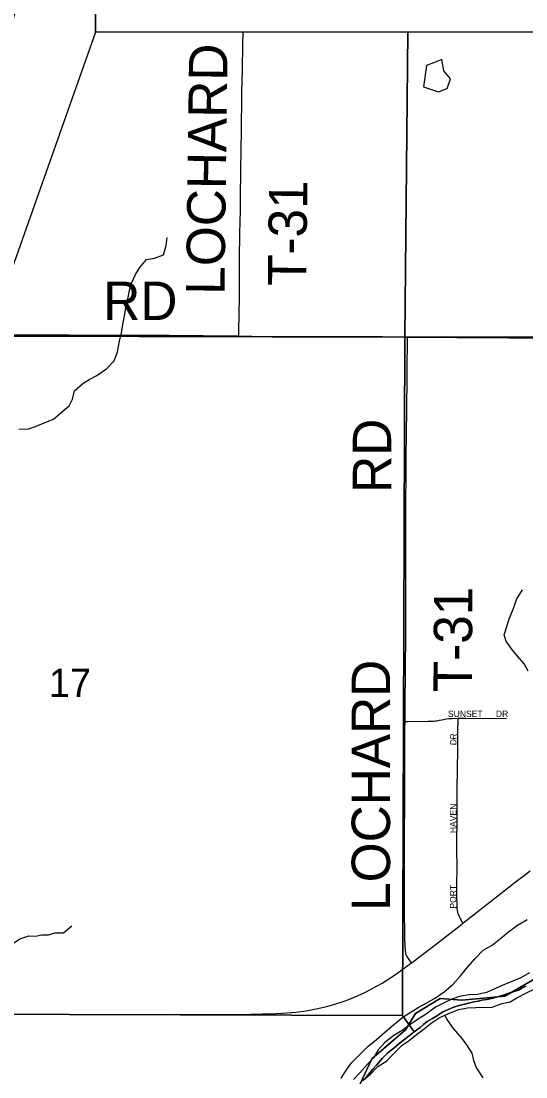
# Model space of a CAD drawing. Extents: x 0 to 1391, y -24 to 440.
# Drawn here: x 572 to 586.94, y 312.9 to 344.14 of the extents above; entities that cross this region are included whole.
import ezdxf

# ---------------------------------------------------------------- set-up
doc = ezdxf.new("R2010")
doc.units = 0
for name, color, linetype in [('GM_X_Major_River', 7, 'Continuous'), ('GM_X_Minor_Lake', 7, 'Continuous'), ('GM_X_Minor_River', 7, 'Continuous'), ('GM_X_Section', 7, 'Continuous'), ('GM_X_Section_Text', 7, 'Continuous'), ('GM_X_State_Route', 7, 'Continuous'), ('GM_X_Township', 7, 'Continuous'), ('GM_X_Township_Road', 7, 'Continuous'), ('GM_X_Township_Road_Text', 7, 'Continuous'), ('GM_X_Township_Subdivision', 7, 'Continuous'), ('GM_X_Township_Subdivision_Text', 7, 'Continuous'), ('SH_Text', 7, 'Continuous')]:
    doc.layers.add(name, color=color, linetype=linetype)

msp = doc.modelspace()

# ---------------------------------------------------------------- linework, layer by layer
at = {"layer": 'GM_X_Major_River'}
for points in [[(587.05, 315.982), (586.795, 315.836), (586.242, 315.606), (586.042, 315.52), (585.78, 315.404), (585.512, 315.343), (585.268, 315.326), (585.009, 315.287), (584.748, 315.202), (584.54, 315.1), (584.263, 314.963), (583.991, 314.756), (583.736, 314.602), (583.535, 314.463), (583.279, 314.271), (583.032, 314.132), (582.769, 313.918), (582.573, 313.702), (582.43, 313.469), (582.258, 313.275), (582.024, 313.022), (581.836, 312.829)], [(582.109, 312.791), (582.334, 312.976), (582.561, 313.207), (582.824, 313.375), (583.027, 313.584), (583.276, 313.837), (583.485, 313.976), (583.703, 314.161), (583.896, 314.293), (584.137, 314.493), (584.377, 314.647), (584.631, 314.77), (584.961, 314.899), (585.213, 314.946), (585.457, 314.955), (585.655, 314.965), (585.914, 314.959), (586.244, 315.073), (586.481, 315.12), (586.674, 315.237), (586.936, 315.383), (587.229, 315.52)]]:
    msp.add_lwpolyline(points, dxfattribs=at)
at = {"layer": 'GM_X_Minor_Lake'}
for points in [[(584.608, 342.141), (584.712, 342.427), (584.513, 342.668), (584.453, 343.005), (584.207, 342.904), (583.999, 342.826)], [(583.999, 342.826), (583.915, 342.189), (584.352, 342.048), (584.608, 342.141)]]:
    msp.add_lwpolyline(points, dxfattribs=at)
at = {"layer": 'GM_X_Minor_River'}
for points in [[(571.938, 332.062), (572.227, 332.07), (572.435, 332.141), (572.689, 332.249), (572.965, 332.356), (573.191, 332.556), (573.424, 332.756), (573.521, 332.951), (573.58, 333.201), (573.829, 333.416), (574.022, 333.532), (574.246, 333.656), (574.533, 333.854), (574.759, 334.085), (574.857, 334.349), (574.911, 334.667), (574.978, 334.917), (575.006, 335.106), (575.058, 335.364), (575.103, 335.644), (575.163, 335.909), (575.208, 336.167), (575.274, 336.386), (575.387, 336.642), (575.522, 336.844), (575.718, 337.083), (575.955, 337.122), (576.216, 337.222), (576.3, 337.494), (576.329, 337.737)], [(587.006, 324.904), (586.889, 325.121), (586.705, 325.339), (586.512, 325.564), (586.358, 325.789), (586.295, 325.981), (586.385, 326.253), (586.451, 326.457), (586.573, 326.758), (586.664, 327.03), (586.838, 327.308)], [(570.273, 315.443), (570.558, 315.85), (570.798, 315.988), (571.038, 316.188), (571.28, 316.403), (571.498, 316.611), (571.693, 316.804), (571.964, 316.988), (572.232, 317.072), (572.43, 317.067), (572.621, 317.108), (572.811, 317.104), (573.003, 317.16), (573.254, 317.169), (573.51, 317.368)], [(581.472, 312.868), (581.638, 313.116), (581.788, 313.325), (582.014, 313.556), (582.263, 313.801), (582.52, 314.008), (582.753, 314.216), (583.025, 314.445), (583.304, 314.667), (583.513, 314.806), (583.753, 314.96), (584.015, 315.091), (584.269, 315.237), (584.525, 315.421), (584.782, 315.635), (585.009, 315.896), (585.228, 316.158), (585.44, 316.404), (585.682, 316.649), (585.944, 316.802), (586.192, 316.994), (586.425, 317.194), (586.697, 317.393), (586.975, 317.554)], [(584.545, 314.729), (584.604, 314.603), (584.787, 314.332), (585.047, 314.043), (585.186, 313.849), (585.34, 313.609), (585.388, 313.387), (585.482, 313.164), (585.672, 312.877)]]:
    msp.add_lwpolyline(points, dxfattribs=at)
at = {"layer": 'GM_X_Section'}
for points in [[(583.446, 343.811), (583.361, 334.79), (563.701, 334.84), (563.869, 355.108), (583.55, 354.883), (583.535, 353.247)], [(603.709, 343.811), (603.356, 334.656), (583.361, 334.79), (583.446, 343.811)], [(586.944, 315.586), (586.822, 315.528), (586.723, 315.469), (586.433, 315.376), (586.265, 315.318), (586.128, 315.282), (585.969, 315.232), (585.786, 315.197), (585.642, 315.17), (585.528, 315.141), (585.406, 315.121), (585.125, 315.05), (584.927, 315.008), (584.782, 314.957), (584.637, 314.892), (584.484, 314.826), (584.323, 314.715), (584.178, 314.627), (584.017, 314.539), (583.91, 314.457), (583.817, 314.368), (583.633, 314.235), (583.286, 314.718), (583.361, 334.79), (603.356, 334.656)], [(582.177, 312.836), (582.286, 312.978), (582.41, 313.127), (582.518, 313.247), (582.626, 313.374), (582.703, 313.456), (582.834, 313.59), (582.911, 313.664), (583.034, 313.753), (583.196, 313.887), (583.364, 314.02), (583.541, 314.161), (583.633, 314.235), (583.817, 314.368), (583.91, 314.457), (584.017, 314.539), (584.178, 314.627), (584.323, 314.715), (584.484, 314.826), (584.637, 314.892), (584.782, 314.957), (584.927, 315.008), (585.125, 315.05), (585.406, 315.121), (585.528, 315.141), (585.642, 315.17), (585.786, 315.197), (585.969, 315.232), (586.128, 315.282), (586.265, 315.318), (586.433, 315.376), (586.723, 315.469), (586.822, 315.528), (586.944, 315.586)], [(563.567, 314.776), (583.286, 314.718), (583.633, 314.235), (583.541, 314.161), (583.364, 314.02), (583.196, 313.887), (583.034, 313.753), (582.911, 313.664), (582.834, 313.59), (582.703, 313.456), (582.626, 313.374), (582.518, 313.247), (582.41, 313.127), (582.286, 312.978), (582.177, 312.836)]]:
    msp.add_lwpolyline(points, dxfattribs=at)
msp.add_lwpolyline([(563.701, 334.84), (583.361, 334.79), (583.286, 314.718), (563.567, 314.776)], close=True, dxfattribs=at)
at = {"layer": 'GM_X_State_Route'}
msp.add_lwpolyline([(571.909, 314.754), (572.477, 314.756), (572.778, 314.754), (574.009, 314.748), (574.991, 314.751), (575.389, 314.753), (576.383, 314.754), (578.111, 314.751), (578.471, 314.752), (579.137, 314.764), (579.353, 314.768), (579.738, 314.785), (580.133, 314.818), (580.44, 314.859), (580.733, 314.912), (581.047, 314.986), (581.321, 315.062), (581.591, 315.154), (581.867, 315.264), (582.191, 315.411), (582.416, 315.525), (582.684, 315.679), (583.051, 315.911), (583.56, 316.28), (583.667, 316.359), (583.807, 316.461), (584.211, 316.772), (584.993, 317.385), (585.076, 317.452), (586.11, 318.255), (586.629, 318.659), (586.825, 318.813), (587.07, 319.003)], dxfattribs=at)
at = {"layer": 'GM_X_Township'}
for points in [[(587.903, 316.211), (586.32, 315.295), (585.045, 315.175), (584.409, 315.218), (583.675, 314.776), (583.38, 314.293), (582.384, 313.435), (581.561, 311.684)], [(581.561, 311.684), (582.384, 313.435), (583.38, 314.293), (583.675, 314.776), (584.409, 315.218), (585.045, 315.175), (586.32, 315.295), (587.903, 316.211)]]:
    msp.add_lwpolyline(points, dxfattribs=at)
at = {"layer": 'GM_X_Township_Road'}
for points in [[(578.444, 334.822), (578.446, 334.966), (578.462, 335.972), (578.466, 336.295), (578.468, 336.692), (578.469, 337.102), (578.481, 337.86), (578.493, 338.531), (578.498, 338.991), (578.509, 339.649), (578.52, 340.394), (578.525, 340.853), (578.524, 341.225), (578.532, 341.623), (578.54, 342.033), (578.554, 342.691), (578.565, 343.449), (578.571, 343.811)], [(563.616, 334.859), (563.902, 334.856), (564.278, 334.852), (565.962, 334.86), (566.632, 334.859), (567.365, 334.861), (568.595, 334.861), (569.217, 334.859), (569.826, 334.859), (570.484, 334.861), (571.677, 334.86), (571.963, 334.859), (572.894, 334.851), (573.428, 334.851), (574.447, 334.846), (575.23, 334.843), (576.398, 334.841), (577.391, 334.837), (577.988, 334.828), (578.444, 334.822)], [(578.444, 334.822), (579.23, 334.811), (580.61, 334.809), (581.355, 334.809), (582.698, 334.803), (583.219, 334.8), (583.436, 334.798)], [(583.366, 323.418), (583.374, 324.123), (583.376, 324.731), (583.379, 325.141), (583.385, 325.813), (583.388, 326.297), (583.387, 326.93), (583.384, 327.725), (583.385, 328.446), (583.387, 329.279), (583.393, 330.024), (583.395, 330.571), (583.402, 331.341), (583.407, 331.838), (583.408, 332.099), (583.414, 332.484), (583.418, 332.857), (583.424, 333.403), (583.426, 333.85), (583.435, 334.695), (583.436, 334.798)], [(583.436, 334.798), (584.487, 334.802), (585.407, 334.801), (586.848, 334.8), (587.805, 334.792)], [(583.56, 316.28), (583.423, 316.47), (583.402, 316.518), (583.388, 316.568), (583.377, 316.643), (583.366, 316.793), (583.36, 316.954), (583.356, 317.278), (583.353, 317.625), (583.348, 318.16), (583.348, 318.806), (583.352, 319.676), (583.353, 319.958), (583.36, 321.141), (583.362, 321.899), (583.364, 322.408), (583.363, 323.191), (583.366, 323.418)]]:
    msp.add_lwpolyline(points, dxfattribs=at)
at = {"layer": 'GM_X_Township_Subdivision'}
for points in [[(583.366, 323.418), (583.434, 323.419), (584.049, 323.423), (584.206, 323.428), (584.271, 323.433), (584.318, 323.439), (584.382, 323.451), (584.45, 323.464), (584.517, 323.479), (584.586, 323.492), (584.65, 323.502), (584.708, 323.508), (584.76, 323.51), (584.934, 323.511)], [(584.913, 321.825), (584.913, 321.839), (584.924, 322.759), (584.929, 323.094), (584.934, 323.511)], [(584.934, 323.511), (585.16, 323.512), (585.827, 323.509), (586.372, 323.511)], [(585.076, 317.452), (584.992, 317.597), (584.965, 317.654), (584.941, 317.722), (584.928, 317.776), (584.92, 317.825), (584.912, 317.888), (584.905, 317.998), (584.899, 318.235), (584.901, 318.633), (584.904, 319.031), (584.901, 319.715), (584.901, 320.013), (584.903, 320.361), (584.905, 320.51), (584.909, 321.044), (584.911, 321.317), (584.911, 321.603), (584.913, 321.825)]]:
    msp.add_lwpolyline(points, dxfattribs=at)
at = {"layer": 'SH_Text'}
for points in [[(563.586, 313.76), (574.209, 353.247), (574.209, 343.811)], [(574.209, 353.247), (615.184, 353.247), (615.184, 343.811), (574.209, 343.811)]]:
    msp.add_lwpolyline(points, close=True, dxfattribs=at)

# ---------------------------------------------------------------- texts
at = {"layer": 'GM_X_Section_Text'}
msp.add_text('17', height=0.8371, rotation=0, dxfattribs=at).set_placement((572.827, 324.142))
at = {"layer": 'GM_X_Township_Road_Text'}
for s, rotation, p in [('LOCHARD', 89.2883, (578.022, 336.035)), ('T-31', 89.3119, (580.441, 336.297)), ('RD', 0, (574.435, 335.294)), ('RD', 90, (582.955, 330.18)), ('T-31', 89.6471, (585.341, 324.278)), ('LOCHARD', 90, (582.922, 317.813))]:
    msp.add_text(s, height=1.1364, rotation=rotation, dxfattribs=at).set_placement(p)
at = {"layer": 'GM_X_Township_Subdivision_Text'}
for s, height, rotation, p in [('SUNSET', 0.1894, 0, (584.635, 323.549)), ('DR', 0.1894, 0, (586.052, 323.549)), ('R', 0.189, 86.6949, (584.89, 322.877)), ('D', 0.189, 87.6386, (584.883, 322.711)), ('HAVEN', 0.1894, 90, (584.883, 320.113)), ('PORT', 0.1894, 90, (584.883, 317.88))]:
    msp.add_text(s, height=height, rotation=rotation, dxfattribs=at).set_placement(p)

doc.saveas('drawing.dxf')
